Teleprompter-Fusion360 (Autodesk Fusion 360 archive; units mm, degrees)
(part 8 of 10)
sketch "Skizze96" plane through (362.0031, 0, 0) normal (-1, 0, 0) x axis (0, -1, 0)
  line L1 (-176.4327, 90.6042) -> (-137.2147, 129.8223)
  line L2 (-156.4445, 183.2864) -> (-195.6625, 104.4333)
  line L3 (-133.7, 138.3075) -> (-133.7, 177.9426)
  line L4 (-97.7, 235.8456) -> (-97.7, 198.3075)
  line L5 (-45.7711, 251.1832) -> (-86.6874, 247.805)
  line L6 (-77.2147, 189.8223) -> (-36.2984, 230.7386)
  line L7 (-117.4574, 213.455) -> (-113.9426, 213.455)
  line L8 (-121.7, 240.7124) -> (-121.7, 217.6976)
  line L9 (-113.9426, 244.955) -> (-117.4574, 244.955)
  line L10 (-109.7, 217.6976) -> (-109.7, 240.7124)
  line L11 (-121.7, 177.7124) -> (-121.7, 154.6976)
  line L12 (-113.9426, 181.955) -> (-117.4574, 181.955)
  line L13 (-109.7, 154.6976) -> (-109.7, 177.7124)
  line L14 (-117.4574, 150.455) -> (-113.9426, 150.455)
  line L15 (16.2993, 266.6485) -> (-239.478, 10.8712)
  line L16 (0.4576, 267) -> (14.6596, 267)
  line L17 (-121.7, 256.955) -> (-0.5298, 266.9593)
  line L18 (-126.9563, 256.521) -> (-123.6681, 256.7925)
  line L19 (-253.9338, 29.6373) -> (-136.5623, 250.199)
  line L20 (-255.3404, 12) -> (-255.3404, 24)
  line L21 (-244.4304, 12) -> (-255.3404, 12)
  line L22 (3.2487, 270) -> (14.6596, 270)
  line L23 (3.2487, 267) -> (3.2487, 270)
  line L24 (14.6596, 267) -> (10.2487, 267)
  line L25 (18.6596, 263.0692) -> (18.659, 263.0698)
  line L26 (18.659, 263.0686) -> (18.6596, 263.0692)
  line L27 (18.6596, 251.0692) -> (18.6596, 263)
  line L28 (15.1903, 238.3866) -> (13.069, 240.508)
  line L29 (17.2662, 240.4626) -> (15.1903, 238.3866)
  line L30 (21.6596, 263) -> (21.6596, 251.0692)
  line L31 (-169.9972, 18) -> (-214.6835, 18)
  line L32 (-164.3404, 0) -> (-164.3404, 14.2357)
  line L33 (-130.1404, 0) -> (-164.3404, 0)
  line L34 (-130.1404, 7.7574) -> (-130.1404, 0)
  line L35 (-100.183, 12) -> (-125.8977, 12)
  line L36 (-95.9404, 0) -> (-95.9404, 7.7574)
  line L37 (-61.7404, 0) -> (-95.9404, 0)
  line L38 (-61.7404, 7.7574) -> (-61.7404, 0)
  line L39 (-31.783, 12) -> (-57.4977, 12)
  line L40 (-27.5404, 0) -> (-27.5404, 7.7574)
  line L41 (6.6596, 0) -> (-27.5404, 0)
  line L42 (6.6596, 15) -> (6.6596, 0)
  line L43 (-58.0916, 27) -> (-5.3404, 27)
  line L44 (-70.0916, 152.3769) -> (-70.0916, 39)
  line L45 (15.1449, 242.5839) -> (-66.5768, 160.8622)
  line L46 (18.6596, 262.7863) -> (18.6596, 251.0692)
  line L47 (-240.1877, 3.939) -> (18.6596, 262.7863)
  line L48 (-240.1877, 0) -> (-240.1877, 3.939)
  line L49 (-220.3404, 0) -> (-240.1877, 0)
  line L50 (-220.3404, 14.2357) -> (-220.3404, 0)
  line L51 (-159.4684, 39) -> (-106.0916, 39)
  line L52 (-114.5768, 112.8622) -> (-167.9537, 59.4853)
  line L53 (-94.0916, 51) -> (-94.0916, 104.3769)
  line L54 (-240.1877, 3.939) -> (-240.1877, 7.7574)
  line L55 (18.6596, 262.7863) -> (-240.1877, 3.939)
  line L56 (18.6596, 263) -> (18.6596, 262.7863)
  line L57 (-239.478, 10.8712) -> (16.2993, 266.6485)
  circle C1 centre (-115.7, 197.705) radius 1.5
  arc A1 centre (-184.918, 99.0895) radius 12 clockwise from (-176.4327, 90.6042) to (-195.6625, 104.4333)
  arc A2 centre (-145.7, 177.9426) radius 12 clockwise from (-156.4445, 183.2864) to (-133.7, 177.9426)
  arc A3 centre (-145.7, 138.3075) radius 12 clockwise from (-133.7, 138.3075) to (-137.2147, 129.8223)
  arc A4 centre (-85.7, 235.8456) radius 12 clockwise from (-97.7, 235.8456) to (-86.6874, 247.805)
  arc A5 centre (-44.7837, 239.2239) radius 12 clockwise from (-45.7711, 251.1832) to (-36.2984, 230.7386)
  arc A6 centre (-85.7, 198.3075) radius 12 clockwise from (-77.2147, 189.8223) to (-97.7, 198.3075)
  arc A7 centre (-119.5787, 215.5763) radius 3 clockwise from (-117.4574, 213.455) to (-121.7, 217.6976)
  arc A8 centre (-119.5787, 242.8337) radius 3 clockwise from (-121.7, 240.7124) to (-117.4574, 244.955)
  arc A9 centre (-111.8213, 242.8337) radius 3 clockwise from (-113.9426, 244.955) to (-109.7, 240.7124)
  arc A10 centre (-111.8213, 215.5763) radius 3 clockwise from (-109.7, 217.6976) to (-113.9426, 213.455)
  arc A11 centre (-119.5787, 179.8337) radius 3 clockwise from (-121.7, 177.7124) to (-117.4574, 181.955)
  arc A12 centre (-111.8213, 179.8337) radius 3 clockwise from (-113.9426, 181.955) to (-109.7, 177.7124)
  arc A13 centre (-111.8213, 152.5763) radius 3 clockwise from (-109.7, 154.6976) to (-113.9426, 150.455)
  arc A14 centre (-119.5787, 152.5763) radius 3 clockwise from (-117.4574, 150.455) to (-121.7, 154.6976)
  arc A15 centre (-242.3091, 9.8787) radius 3 clockwise from (-244.4304, 12) to (-239.478, 10.8712)
  arc A16 centre (14.6596, 263) radius 4 clockwise from (14.6596, 267) to (16.2993, 266.6485)
  arc A17 centre (0.4576, 255) radius 12 clockwise from (-0.5298, 266.9593) to (0.4576, 267)
  arc A18 centre (-121.7, 244.955) radius 12 clockwise from (-123.6681, 256.7925) to (-121.7, 256.955)
  arc A19 centre (-125.9689, 244.5617) radius 12 clockwise from (-136.5623, 250.199) to (-126.9563, 256.521)
  arc A20 centre (-243.3404, 24) radius 12 clockwise from (-255.3404, 24) to (-253.9338, 29.6373)
  arc A21 centre (14.6596, 263) radius 7 clockwise from (14.6596, 270) to (21.6596, 263)
  arc A22 centre (6.7487, 267) radius 3.5 clockwise from (10.2487, 267) to (3.2487, 267)
  arc A23 centre (14.6596, 263) radius 4 clockwise from (14.6596, 267) to (18.659, 263.0698)
  arc A24 centre (14.6596, 263) radius 4 clockwise from (18.659, 263.0686) to (18.6596, 263)
  arc A25 centre (6.6596, 251.0692) radius 12 clockwise from (18.6596, 251.0692) to (17.4864, 245.8942)
  arc A26 centre (15.5438, 242.9828) radius 3.5 clockwise from (13.069, 240.508) to (17.4864, 245.8942)
  arc A27 centre (6.6596, 251.0692) radius 15 clockwise from (21.6596, 251.0692) to (17.2662, 240.4626)
  arc A28 centre (6.7487, 267) radius 3.75 clockwise from (10.4987, 267) to (2.9987, 267)
  circle C2 centre (15.5438, 242.9828) radius 3.75
  arc A29 centre (-214.6835, 10) radius 8 clockwise from (-218.9345, 16.7771) to (-214.6835, 18)
  arc A30 centre (-169.9972, 10) radius 8 clockwise from (-169.9972, 18) to (-165.7463, 16.7771)
  arc A31 centre (-167.3404, 14.2357) radius 3 clockwise from (-165.7463, 16.7771) to (-164.3404, 14.2357)
  arc A32 centre (-128.0191, 9.8787) radius 3 clockwise from (-130.1404, 7.7574) to (-125.8977, 12)
  arc A33 centre (-98.0617, 9.8787) radius 3 clockwise from (-100.183, 12) to (-95.9404, 7.7574)
  arc A34 centre (-59.6191, 9.8787) radius 3 clockwise from (-61.7404, 7.7574) to (-57.4977, 12)
  arc A35 centre (-29.6617, 9.8787) radius 3 clockwise from (-31.783, 12) to (-27.5404, 7.7574)
  arc A36 centre (-5.3404, 15) radius 12 clockwise from (-5.3404, 27) to (6.6596, 15)
  arc A37 centre (-58.0916, 39) radius 12 clockwise from (-58.0916, 27) to (-70.0916, 39)
  arc A38 centre (-58.0916, 152.3769) radius 12 clockwise from (-70.0916, 152.3769) to (-66.5768, 160.8622)
  arc A39 centre (6.6596, 251.0692) radius 12 clockwise from (18.6596, 251.0692) to (15.1449, 242.5839)
  arc A40 centre (-217.3404, 14.2357) radius 3 clockwise from (-220.3404, 14.2357) to (-218.9345, 16.7771)
  circle C3 centre (-140.2404, 6) radius 1.5
  arc A41 centre (-159.4684, 51) radius 12 clockwise from (-159.4684, 39) to (-167.9537, 59.4853)
  arc A42 centre (-106.0916, 104.3769) radius 12 clockwise from (-114.5768, 112.8622) to (-94.0916, 104.3769)
  arc A43 centre (-106.0916, 51) radius 12 clockwise from (-94.0916, 51) to (-106.0916, 39)
  circle C4 centre (-230.2641, 6) radius 1.5
  circle C5 centre (-10.4404, 6) radius 1.5
  circle C6 centre (-78.8404, 6) radius 1.5
  arc A44 centre (-242.3091, 9.8787) radius 3 clockwise from (-239.478, 10.8712) to (-240.1877, 7.7574)
  arc A45 centre (14.6596, 263) radius 4 clockwise from (16.2993, 266.6485) to (18.6596, 263)
  point P85 (10.4987, 267)
  point P86 (2.9987, 267)
  concentric A22 A28
  coincident L16 P85
  coincident L16 P86
  concentric A26 C2
  dimension "d545" diameter A28 = 7.5
  dimension "d547" diameter C2 = 7.5
extrude "Extrusion97" cut sketch "Skizze96" profile of L16 A22 L24 A25 A26 A28 C2 L45 A39 against normal blind 14
mirror "Spiegeln4" mirrorStitchTolerance 0.1 bodies "3DP-Glas-Abdeckung Left"
sketch "Skizze97" plane through (-2.9969, 0, 0) normal (1, 0, 0) x axis (0, 1, 0)
  line L1 (137.2147, 129.8223) -> (176.4327, 90.6042)
  line L2 (133.7, 177.9426) -> (133.7, 138.3075)
  line L3 (195.6625, 104.4333) -> (156.4445, 183.2864)
  line L4 (97.7, 198.3075) -> (97.7, 235.8456)
  line L5 (36.2984, 230.7386) -> (77.2147, 189.8223)
  line L6 (86.6874, 247.805) -> (45.7711, 251.1832)
  line L7 (113.9426, 213.455) -> (117.4574, 213.455)
  line L8 (109.7, 240.7124) -> (109.7, 217.6976)
  line L9 (117.4574, 244.955) -> (113.9426, 244.955)
  line L10 (121.7, 217.6976) -> (121.7, 240.7124)
  line L11 (121.7, 154.6976) -> (121.7, 177.7124)
  line L12 (113.9426, 150.455) -> (117.4574, 150.455)
  line L13 (109.7, 177.7124) -> (109.7, 154.6976)
  line L14 (117.4574, 181.955) -> (113.9426, 181.955)
  line L15 (255.3404, 12) -> (244.4304, 12)
  line L16 (255.3404, 24) -> (255.3404, 12)
  line L17 (136.5623, 250.199) -> (253.9338, 29.6373)
  line L18 (123.6681, 256.7925) -> (126.9563, 256.521)
  line L19
  line L20 (-14.6596, 267) -> (-0.4576, 267)
  line L21 (239.478, 10.8712) -> (-16.2993, 266.6485)
  line L22 (106.0916, 39) -> (159.4684, 39)
  line L23 (94.0916, 104.3769) -> (94.0916, 51)
  line L24 (167.9537, 59.4853) -> (114.5768, 112.8622)
  line L25 (130.1404, 0) -> (130.1404, 7.7574)
  line L26 (164.3404, 0) -> (130.1404, 0)
  line L27 (164.3404, 11.3932) -> (164.3404, 0)
  line L28 (214.6835, 16) -> (169.9972, 16)
  line L29 (220.3404, 0) -> (220.3404, 11.3932)
  line L30 (240.1877, 0) -> (220.3404, 0)
  line L31 (240.1877, 3.939) -> (240.1877, 0)
  line L32 (-18.6596, 262.7863) -> (240.1877, 3.939)
  line L33 (-18.6596, 251.0692) -> (-18.6596, 262.7863)
  line L34 (66.5768, 160.8622) -> (-15.1449, 242.5839)
  line L35 (70.0916, 39) -> (70.0916, 152.3769)
  line L36 (5.3404, 27) -> (58.0916, 27)
  line L37 (-6.6596, 0) -> (-6.6596, 15)
  line L38 (27.5404, 0) -> (-6.6596, 0)
  line L39 (27.5404, 7.7574) -> (27.5404, 0)
  line L40 (57.4977, 12) -> (31.783, 12)
  line L41 (61.7404, 0) -> (61.7404, 7.7574)
  line L42 (95.9404, 0) -> (61.7404, 0)
  line L43 (95.9404, 7.7574) -> (95.9404, 0)
  line L44 (125.8977, 12) -> (100.183, 12)
  line L45 (-16.2993, 266.6485) -> (239.478, 10.8712)
  line L46 (-18.6596, 262.7863) -> (-18.6596, 263)
  line L47 (240.1877, 3.939) -> (-18.6596, 262.7863)
  line L48 (240.1877, 7.7574) -> (240.1877, 3.939)
  circle C1 centre (115.7, 197.705) radius 1.5
  arc A1 centre (145.7, 138.3075) radius 12 clockwise from (137.2147, 129.8223) to (133.7, 138.3075)
  arc A2 centre (145.7, 177.9426) radius 12 clockwise from (133.7, 177.9426) to (156.4445, 183.2864)
  arc A3 centre (184.918, 99.0895) radius 12 clockwise from (195.6625, 104.4333) to (176.4327, 90.6042)
  arc A4 centre (85.7, 198.3075) radius 12 clockwise from (97.7, 198.3075) to (77.2147, 189.8223)
  arc A5 centre (44.7837, 239.2239) radius 12 clockwise from (36.2984, 230.7386) to (45.7711, 251.1832)
  arc A6 centre (85.7, 235.8456) radius 12 clockwise from (86.6874, 247.805) to (97.7, 235.8456)
  arc A7 centre (111.8213, 215.5763) radius 3 clockwise from (113.9426, 213.455) to (109.7, 217.6976)
  arc A8 centre (111.8213, 242.8337) radius 3 clockwise from (109.7, 240.7124) to (113.9426, 244.955)
  arc A9 centre (119.5787, 242.8337) radius 3 clockwise from (117.4574, 244.955) to (121.7, 240.7124)
  arc A10 centre (119.5787, 215.5763) radius 3 clockwise from (121.7, 217.6976) to (117.4574, 213.455)
  arc A11 centre (119.5787, 152.5763) radius 3 clockwise from (121.7, 154.6976) to (117.4574, 150.455)
  arc A12 centre (111.8213, 152.5763) radius 3 clockwise from (113.9426, 150.455) to (109.7, 154.6976)
  arc A13 centre (111.8213, 179.8337) radius 3 clockwise from (109.7, 177.7124) to (113.9426, 181.955)
  arc A14 centre (119.5787, 179.8337) radius 3 clockwise from (117.4574, 181.955) to (121.7, 177.7124)
  arc A15 centre (242.3091, 9.8787) radius 3 clockwise from (239.478, 10.8712) to (244.4304, 12)
  arc A16 centre (243.3404, 24) radius 12 clockwise from (253.9338, 29.6373) to (255.3404, 24)
  arc A17 centre (125.9689, 244.5617) radius 12 clockwise from (126.9563, 256.521) to (136.5623, 250.199)
  arc A18 centre (121.7, 244.955) radius 12 clockwise from (121.7, 256.955) to (123.6681, 256.7925)
  arc A19 centre (-0.4576, 255) radius 12 clockwise from (-0.4576, 267) to (0.5298, 266.9593)
  arc A20 centre (-14.6596, 263) radius 4 clockwise from (-16.2993, 266.6485) to (-14.6596, 267)
  arc A21 centre (-6.7487, 267) radius 3.75 clockwise from (-2.9987, 267) to (-10.4987, 267)
  arc A22 centre (-15.5438, 242.9828) radius 3.75 clockwise from (-17.593, 246.1234) to (-12.8922, 240.3312)
  circle C2 centre (140.2404, 6) radius 1.5
  arc A23 centre (106.0916, 51) radius 12 clockwise from (106.0916, 39) to (94.0916, 51)
  arc A24 centre (106.0916, 104.3769) radius 12 clockwise from (94.0916, 104.3769) to (114.5768, 112.8622)
  arc A25 centre (159.4684, 51) radius 12 clockwise from (167.9537, 59.4853) to (159.4684, 39)
  circle C3 centre (230.2641, 6) radius 1.5
  circle C4 centre (10.4404, 6) radius 1.5
  circle C5 centre (78.8404, 6) radius 1.5
  arc A26 centre (128.0191, 9.8787) radius 3 clockwise from (125.8977, 12) to (130.1404, 7.7574)
  arc A27 centre (167.3404, 11.3932) radius 3 clockwise from (164.3404, 11.3932) to (164.6835, 12.7865)
  arc A28 centre (169.9972, 10) radius 6 clockwise from (164.6835, 12.7865) to (169.9972, 16)
  arc A29 centre (214.6835, 10) radius 6 clockwise from (214.6835, 16) to (219.9972, 12.7865)
  arc A30 centre (217.3404, 11.3932) radius 3 clockwise from (219.9972, 12.7865) to (220.3404, 11.3932)
  arc A31 centre (-6.6596, 251.0692) radius 12 clockwise from (-15.1449, 242.5839) to (-18.6596, 251.0692)
  arc A32 centre (58.0916, 152.3769) radius 12 clockwise from (66.5768, 160.8622) to (70.0916, 152.3769)
  arc A33 centre (58.0916, 39) radius 12 clockwise from (70.0916, 39) to (58.0916, 27)
  arc A34 centre (5.3404, 15) radius 12 clockwise from (-6.6596, 15) to (5.3404, 27)
  arc A35 centre (29.6617, 9.8787) radius 3 clockwise from (27.5404, 7.7574) to (31.783, 12)
  arc A36 centre (59.6191, 9.8787) radius 3 clockwise from (57.4977, 12) to (61.7404, 7.7574)
  arc A37 centre (98.0617, 9.8787) radius 3 clockwise from (95.9404, 7.7574) to (100.183, 12)
  arc A38 centre (242.3091, 9.8787) radius 3 clockwise from (240.1877, 7.7574) to (239.478, 10.8712)
  arc A39 centre (-14.6596, 263) radius 4 clockwise from (-18.6596, 263) to (-16.2993, 266.6485)
extrude "Extrusion98" cut sketch "Skizze97" profile of L20 A21 A22 A31 L34 against normal blind 16
chamfer "Fase12" distance 2 distance 6
chamfer "Fase13" distance 6 distance 2
sketch "Skizze98" plane through (0, 0, 0) normal (0, 0, -1) x axis (1, 0, 0)
  line L1 (47.0031, -126.3404) -> (155.5031, -126.3404)
  line L2 (35.0031, -31.3404) -> (35.0031, -114.3404)
  line L3 (155.5031, -19.3404) -> (47.0031, -19.3404)
  line L4 (167.5031, -114.3404) -> (167.5031, -31.3404)
  line L5 (71.0031, -202.3404) -> (155.5031, -202.3404)
  line L6 (59.0031, -174.3404) -> (59.0031, -190.3404)
  line L7 (155.5031, -162.3404) -> (71.0031, -162.3404)
  line L8 (167.5031, -190.3404) -> (167.5031, -174.3404)
  line L9 (191.5031, -31.3404) -> (191.5031, -114.3404)
  line L10 (312.0031, -19.3404) -> (203.5031, -19.3404)
  line L11 (324.0031, -114.3404) -> (324.0031, -31.3404)
  line L12 (203.5031, -126.3404) -> (312.0031, -126.3404)
  line L13 (300.0031, -190.3404) -> (300.0031, -174.3404)
  line L14 (203.5031, -202.3404) -> (288.0031, -202.3404)
  line L15 (191.5031, -174.3404) -> (191.5031, -190.3404)
  line L16 (288.0031, -162.3404) -> (203.5031, -162.3404)
  line L17 (137.0031, -323.7) -> (137.0031, -279.3404)
  line L18 (154.0031, -323.7) -> (137.0031, -323.7)
  line L19 (154.0031, -311.7) -> (154.0031, -323.7)
  line L20 (171.0031, -311.7) -> (154.0031, -311.7)
  line L21 (171.0031, -323.7) -> (171.0031, -311.7)
  line L22 (188.0031, -323.7) -> (171.0031, -323.7)
  line L23 (188.0031, -311.7) -> (188.0031, -323.7)
  line L24 (205.0031, -311.7) -> (188.0031, -311.7)
  line L25 (205.0031, -323.7) -> (205.0031, -311.7)
  line L26 (222.0031, -323.7) -> (205.0031, -323.7)
  line L27 (222.0031, -279.3404) -> (222.0031, -323.7)
  line L28 (374.0031, -255.3404) -> (246.0031, -255.3404)
  line L29 (374.0031, -240.1877) -> (374.0031, -255.3404)
  line L30 (366.2457, -240.1877) -> (374.0031, -240.1877)
  line L31 (362.0031, -220.3404) -> (362.0031, -235.9451)
  line L32 (361.0031, -220.3404) -> (362.0031, -220.3404)
  line L33 (358.0031, -167.3404) -> (358.0031, -217.3404)
  line L34 (362.0031, -164.3404) -> (361.0031, -164.3404)
  line L35 (362.0031, -134.383) -> (362.0031, -164.3404)
  line L36 (374.0031, -130.1404) -> (366.2457, -130.1404)
  line L37 (374.0031, -95.9404) -> (374.0031, -130.1404)
  line L38 (366.2457, -95.9404) -> (374.0031, -95.9404)
  line L39 (362.0031, -65.983) -> (362.0031, -91.6977)
  line L40 (374.0031, -61.7404) -> (366.2457, -61.7404)
  line L41 (374.0031, -27.5404) -> (374.0031, -61.7404)
  line L42 (366.2457, -27.5404) -> (374.0031, -27.5404)
  line L43 (362.0031, 2.417) -> (362.0031, -23.2977)
  line L44 (374.0031, 6.6596) -> (366.2457, 6.6596)
  line L45 (-2.9969, 18.6596) -> (362.0031, 18.6596)
  line L46 (-7.2396, 6.6596) -> (-14.9969, 6.6596)
  line L47 (-2.9969, -23.2977) -> (-2.9969, 2.417)
  line L48 (-14.9969, -27.5404) -> (-7.2396, -27.5404)
  line L49 (-14.9969, -61.7404) -> (-14.9969, -27.5404)
  line L50 (-7.2396, -61.7404) -> (-14.9969, -61.7404)
  line L51 (-2.9969, -91.6977) -> (-2.9969, -65.983)
  line L52 (-14.9969, -95.9404) -> (-7.2396, -95.9404)
  line L53 (-14.9969, -130.1404) -> (-14.9969, -95.9404)
  line L54 (-7.2396, -130.1404) -> (-14.9969, -130.1404)
  line L55 (-2.9969, -164.3404) -> (-2.9969, -134.383)
  line L56 (-2.9968, -164.3404) -> (-2.9969, -164.3404)
  line L57 (0.0031, -217.3404) -> (0.0031, -167.3404)
  line L58 (-2.9969, -220.3404) -> (-2.9968, -220.3404)
  line L59 (-2.9969, -235.9451) -> (-2.9969, -220.3404)
  line L60 (-14.9969, -240.1877) -> (-7.2396, -240.1877)
  line L61 (-14.9969, -255.3404) -> (-14.9969, -240.1877)
  line L62 (113.0031, -255.3404) -> (-14.9969, -255.3404)
  circle C1 centre (-8.9969, -113.0404) radius 4.5
  circle C2 centre (368.0031, -246.1877) radius 4.5
  circle C3 centre (368.0031, -44.6404) radius 4.5
  circle C4 centre (179.5031, -317.7) radius 4.5
  arc A1 centre (47.0031, -114.3404) radius 12 clockwise from (47.0031, -126.3404) to (35.0031, -114.3404)
  arc A2 centre (47.0031, -31.3404) radius 12 clockwise from (35.0031, -31.3404) to (47.0031, -19.3404)
  arc A3 centre (155.5031, -31.3404) radius 12 clockwise from (155.5031, -19.3404) to (167.5031, -31.3404)
  arc A4 centre (155.5031, -114.3404) radius 12 clockwise from (167.5031, -114.3404) to (155.5031, -126.3404)
  arc A5 centre (71.0031, -190.3404) radius 12 clockwise from (71.0031, -202.3404) to (59.0031, -190.3404)
  arc A6 centre (71.0031, -174.3404) radius 12 clockwise from (59.0031, -174.3404) to (71.0031, -162.3404)
  arc A7 centre (155.5031, -174.3404) radius 12 clockwise from (155.5031, -162.3404) to (167.5031, -174.3404)
  arc A8 centre (155.5031, -190.3404) radius 12 clockwise from (167.5031, -190.3404) to (155.5031, -202.3404)
  arc A9 centre (203.5031, -31.3404) radius 12 clockwise from (191.5031, -31.3404) to (203.5031, -19.3404)
  arc A10 centre (312.0031, -31.3404) radius 12 clockwise from (312.0031, -19.3404) to (324.0031, -31.3404)
  arc A11 centre (312.0031, -114.3404) radius 12 clockwise from (324.0031, -114.3404) to (312.0031, -126.3404)
  arc A12 centre (203.5031, -114.3404) radius 12 clockwise from (203.5031, -126.3404) to (191.5031, -114.3404)
  arc A13 centre (288.0031, -190.3404) radius 12 clockwise from (300.0031, -190.3404) to (288.0031, -202.3404)
  arc A14 centre (203.5031, -190.3404) radius 12 clockwise from (203.5031, -202.3404) to (191.5031, -190.3404)
  arc A15 centre (203.5031, -174.3404) radius 12 clockwise from (191.5031, -174.3404) to (203.5031, -162.3404)
  arc A16 centre (288.0031, -174.3404) radius 12 clockwise from (288.0031, -162.3404) to (300.0031, -174.3404)
  arc A17 centre (246.0031, -279.3404) radius 24 clockwise from (222.0031, -279.3404) to (246.0031, -255.3404)
  arc A18 centre (364.1244, -238.0664) radius 3 clockwise from (366.2457, -240.1877) to (362.0031, -235.9451)
  arc A19 centre (361.0031, -217.3404) radius 3 clockwise from (361.0031, -220.3404) to (358.0031, -217.3404)
  arc A20 centre (361.0031, -167.3404) radius 3 clockwise from (358.0031, -167.3404) to (361.0031, -164.3404)
  arc A21 centre (364.1244, -132.2617) radius 3 clockwise from (362.0031, -134.383) to (366.2457, -130.1404)
  arc A22 centre (364.1244, -93.8191) radius 3 clockwise from (366.2457, -95.9404) to (362.0031, -91.6977)
  arc A23 centre (364.1244, -63.8617) radius 3 clockwise from (362.0031, -65.983) to (366.2457, -61.7404)
  arc A24 centre (364.1244, -25.4191) radius 3 clockwise from (366.2457, -27.5404) to (362.0031, -23.2977)
  arc A25 centre (364.1244, 4.5383) radius 3 clockwise from (362.0031, 2.417) to (366.2457, 6.6596)
  arc A26 centre (362.0031, 6.6596) radius 12 clockwise from (362.0031, 18.6596) to (374.0031, 6.6596)
  arc A27 centre (-2.9969, 6.6596) radius 12 clockwise from (-14.9969, 6.6596) to (-2.9969, 18.6596)
  arc A28 centre (-5.1183, 4.5383) radius 3 clockwise from (-7.2396, 6.6596) to (-2.9969, 2.417)
  arc A29 centre (-5.1183, -25.4191) radius 3 clockwise from (-2.9969, -23.2977) to (-7.2396, -27.5404)
  arc A30 centre (-5.1183, -63.8617) radius 3 clockwise from (-7.2396, -61.7404) to (-2.9969, -65.983)
  arc A31 centre (-5.1183, -93.8191) radius 3 clockwise from (-2.9969, -91.6977) to (-7.2396, -95.9404)
  arc A32 centre (-5.1183, -132.2617) radius 3 clockwise from (-7.2396, -130.1404) to (-2.9969, -134.383)
  arc A33 centre (-2.9969, -167.3404) radius 3 clockwise from (-2.9968, -164.3404) to (0.0031, -167.3404)
  arc A34 centre (-2.9969, -217.3404) radius 3 clockwise from (0.0031, -217.3404) to (-2.9968, -220.3404)
  arc A35 centre (-5.1183, -238.0664) radius 3 clockwise from (-2.9969, -235.9451) to (-7.2396, -240.1877)
  arc A36 centre (113.0031, -279.3404) radius 24 clockwise from (113.0031, -255.3404) to (137.0031, -279.3404)
  circle C5 centre (213.5031, -317.7) radius 4.5
  circle C6 centre (145.5031, -317.7) radius 4.5
  circle C7 centre (368.0031, -113.0404) radius 4.5
  circle C8 centre (-8.9969, -44.6404) radius 4.5
  circle C9 centre (-8.9969, -246.1877) radius 4.5
extrude "Extrusion99" add sketch "Skizze98" profile of L5 A5 L6 A6 L7 A7 L8 A8 L13 A13 L14 A14 L15 A15 L16 A16 to an object
sketch "Skizze99" plane through (0, 0, 0) normal (0, 0, -1) x axis (1, 0, 0)
  line L1 (47.0031, -126.3404) -> (155.5031, -126.3404)
  line L2 (35.0031, -31.3404) -> (35.0031, -114.3404)
  line L3 (155.5031, -19.3404) -> (47.0031, -19.3404)
  line L4 (167.5031, -114.3404) -> (167.5031, -31.3404)
  line L5 (191.5031, -31.3404) -> (191.5031, -114.3404)
  line L6 (312.0031, -19.3404) -> (203.5031, -19.3404)
  line L7 (324.0031, -114.3404) -> (324.0031, -31.3404)
  line L8 (203.5031, -126.3404) -> (312.0031, -126.3404)
  line L9 (137.0031, -323.7) -> (137.0031, -279.3404)
  line L10 (154.0031, -323.7) -> (137.0031, -323.7)
  line L11 (154.0031, -311.7) -> (154.0031, -323.7)
  line L12 (171.0031, -311.7) -> (154.0031, -311.7)
  line L13 (171.0031, -323.7) -> (171.0031, -311.7)
  line L14 (188.0031, -323.7) -> (171.0031, -323.7)
  line L15 (188.0031, -311.7) -> (188.0031, -323.7)
  line L16 (205.0031, -311.7) -> (188.0031, -311.7)
  line L17 (205.0031, -323.7) -> (205.0031, -311.7)
  line L18 (222.0031, -323.7) -> (205.0031, -323.7)
  line L19 (222.0031, -279.3404) -> (222.0031, -323.7)
  line L20 (374.0031, -255.3404) -> (246.0031, -255.3404)
  line L21 (374.0031, -240.1877) -> (374.0031, -255.3404)
  line L22 (366.2457, -240.1877) -> (374.0031, -240.1877)
  line L23 (362.0031, -220.3404) -> (362.0031, -235.9451)
  line L24 (361.0031, -220.3404) -> (362.0031, -220.3404)
  line L25 (358.0031, -167.3404) -> (358.0031, -217.3404)
  line L26 (362.0031, -164.3404) -> (361.0031, -164.3404)
  line L27 (362.0031, -134.383) -> (362.0031, -164.3404)
  line L28 (374.0031, -130.1404) -> (366.2457, -130.1404)
  line L29 (374.0031, -95.9404) -> (374.0031, -130.1404)
  line L30 (366.2457, -95.9404) -> (374.0031, -95.9404)
  line L31 (362.0031, -65.983) -> (362.0031, -91.6977)
  line L32 (374.0031, -61.7404) -> (366.2457, -61.7404)
  line L33 (374.0031, -27.5404) -> (374.0031, -61.7404)
  line L34 (366.2457, -27.5404) -> (374.0031, -27.5404)
  line L35 (362.0031, 2.417) -> (362.0031, -23.2977)
  line L36 (374.0031, 6.6596) -> (366.2457, 6.6596)
  line L37 (-2.9969, 18.6596) -> (362.0031, 18.6596)
  line L38 (-7.2396, 6.6596) -> (-14.9969, 6.6596)
  line L39 (-2.9969, -23.2977) -> (-2.9969, 2.417)
  line L40 (-14.9969, -27.5404) -> (-7.2396, -27.5404)
  line L41 (-14.9969, -61.7404) -> (-14.9969, -27.5404)
  line L42 (-7.2396, -61.7404) -> (-14.9969, -61.7404)
  line L43 (-2.9969, -91.6977) -> (-2.9969, -65.983)
  line L44 (-14.9969, -95.9404) -> (-7.2396, -95.9404)
  line L45 (-14.9969, -130.1404) -> (-14.9969, -95.9404)
  line L46 (-7.2396, -130.1404) -> (-14.9969, -130.1404)
  line L47 (-2.9969, -164.3404) -> (-2.9969, -134.383)
  line L48 (-2.9968, -164.3404) -> (-2.9969, -164.3404)
  line L49 (0.0031, -217.3404) -> (0.0031, -167.3404)
  line L50 (-2.9969, -220.3404) -> (-2.9968, -220.3404)
  line L51 (-2.9969, -235.9451) -> (-2.9969, -220.3404)
  line L52 (-14.9969, -240.1877) -> (-7.2396, -240.1877)
  line L53 (-14.9969, -255.3404) -> (-14.9969, -240.1877)
  line L54 (113.0031, -255.3404) -> (-14.9969, -255.3404)
  line L55 (282.0031, -255.3404) -> (77.0031, -255.3404)
  line L56 (282.0031, -126.3404) -> (282.0031, -255.3404)
  line L57 (77.0031, -126.3404) -> (282.0031, -126.3404)
  line L58 (77.0031, -255.3404) -> (77.0031, -126.3404)
  line L59 (222.0031, -290.3404) -> (137.0031, -290.3404)
  line L60 (191.5031, -91.3404) -> (167.5031, -91.3404)
  circle C1 centre (-8.9969, -113.0404) radius 4.5
  circle C2 centre (368.0031, -246.1877) radius 4.5
  circle C3 centre (368.0031, -44.6404) radius 4.5
  circle C4 centre (179.5031, -317.7) radius 4.5
  arc A1 centre (47.0031, -114.3404) radius 12 clockwise from (47.0031, -126.3404) to (35.0031, -114.3404)
  arc A2 centre (47.0031, -31.3404) radius 12 clockwise from (35.0031, -31.3404) to (47.0031, -19.3404)
  arc A3 centre (155.5031, -31.3404) radius 12 clockwise from (155.5031, -19.3404) to (167.5031, -31.3404)
  arc A4 centre (155.5031, -114.3404) radius 12 clockwise from (167.5031, -114.3404) to (155.5031, -126.3404)
  arc A5 centre (203.5031, -31.3404) radius 12 clockwise from (191.5031, -31.3404) to (203.5031, -19.3404)
  arc A6 centre (312.0031, -31.3404) radius 12 clockwise from (312.0031, -19.3404) to (324.0031, -31.3404)
  arc A7 centre (312.0031, -114.3404) radius 12 clockwise from (324.0031, -114.3404) to (312.0031, -126.3404)
  arc A8 centre (203.5031, -114.3404) radius 12 clockwise from (203.5031, -126.3404) to (191.5031, -114.3404)
  arc A9 centre (246.0031, -279.3404) radius 24 clockwise from (222.0031, -279.3404) to (246.0031, -255.3404)
  arc A10 centre (364.1244, -238.0664) radius 3 clockwise from (366.2457, -240.1877) to (362.0031, -235.9451)
  arc A11 centre (361.0031, -217.3404) radius 3 clockwise from (361.0031, -220.3404) to (358.0031, -217.3404)
  arc A12 centre (361.0031, -167.3404) radius 3 clockwise from (358.0031, -167.3404) to (361.0031, -164.3404)
  arc A13 centre (364.1244, -132.2617) radius 3 clockwise from (362.0031, -134.383) to (366.2457, -130.1404)
  arc A14 centre (364.1244, -93.8191) radius 3 clockwise from (366.2457, -95.9404) to (362.0031, -91.6977)
  arc A15 centre (364.1244, -63.8617) radius 3 clockwise from (362.0031, -65.983) to (366.2457, -61.7404)
  arc A16 centre (364.1244, -25.4191) radius 3 clockwise from (366.2457, -27.5404) to (362.0031, -23.2977)
  arc A17 centre (364.1244, 4.5383) radius 3 clockwise from (362.0031, 2.417) to (366.2457, 6.6596)
  arc A18 centre (362.0031, 6.6596) radius 12 clockwise from (362.0031, 18.6596) to (374.0031, 6.6596)
  arc A19 centre (-2.9969, 6.6596) radius 12 clockwise from (-14.9969, 6.6596) to (-2.9969, 18.6596)
  arc A20 centre (-5.1183, 4.5383) radius 3 clockwise from (-7.2396, 6.6596) to (-2.9969, 2.417)
  arc A21 centre (-5.1183, -25.4191) radius 3 clockwise from (-2.9969, -23.2977) to (-7.2396, -27.5404)
  arc A22 centre (-5.1183, -63.8617) radius 3 clockwise from (-7.2396, -61.7404) to (-2.9969, -65.983)
  arc A23 centre (-5.1183, -93.8191) radius 3 clockwise from (-2.9969, -91.6977) to (-7.2396, -95.9404)
  arc A24 centre (-5.1183, -132.2617) radius 3 clockwise from (-7.2396, -130.1404) to (-2.9969, -134.383)
  arc A25 centre (-2.9969, -167.3404) radius 3 clockwise from (-2.9968, -164.3404) to (0.0031, -167.3404)
  arc A26 centre (-2.9969, -217.3404) radius 3 clockwise from (0.0031, -217.3404) to (-2.9968, -220.3404)
  arc A27 centre (-5.1183, -238.0664) radius 3 clockwise from (-2.9969, -235.9451) to (-7.2396, -240.1877)
  arc A28 centre (113.0031, -279.3404) radius 24 clockwise from (113.0031, -255.3404) to (137.0031, -279.3404)
  circle C5 centre (213.5031, -317.7) radius 4.5
  circle C6 centre (145.5031, -317.7) radius 4.5
  circle C7 centre (368.0031, -113.0404) radius 4.5
  circle C8 centre (-8.9969, -44.6404) radius 4.5
  circle C9 centre (-8.9969, -246.1877) radius 4.5
  point P123 (282.0031, -126.3404)
  point P121 (77.0031, -255.3404)
  point P125 (137.0031, -290.3404)
  point P126 (222.0031, -290.3404)
  point P127 (167.5031, -91.3404)
  point P128 (191.5031, -91.3404)
  horizontal L55
  vertical L56
  horizontal L57
  vertical L58
  coincident L8 P123
  coincident L54 P121
  coincident L9 P125
  coincident L19 P126
  perpendicular L19 L59
  coincident L4 P127
  coincident L5 P128
  perpendicular L5 L60
  dimension "d560" distance L27 L56 = 80
  dimension "d561" distance L47 L58 = 80
  dimension "d562" distance L55 L59 = 35
  dimension "d563" distance L57 L60 = 35
extrude "Extrusion100" new body sketch "Skizze99" profile of L1 L4 A4 L5 L8 A8 L9 L19 A9 L20 L54 A28 L56 L57 L58 L59 L60 along normal blind 12 bodies "Stiffening Base Adapter"
component_insert "Komponente einfügen3"
sketch "Skizze100" plane through (0, 0, 4) normal (0, 0, 1) x axis (-1, 0, 0)
  line L1 (2.9968, -220.3404) -> (2.9969, -220.3404)
  line L2 (-0.0031, -167.3404) -> (-0.0031, -217.3404)
  line L3 (2.9969, -164.3404) -> (2.9968, -164.3404)
  line L4 (2.9969, -150.3404) -> (2.9969, -164.3404)
  line L5 (-362.0031, -150.3404) -> (2.9969, -150.3404)
  line L6 (-362.0031, -164.3404) -> (-362.0031, -150.3404)
  line L7 (-361.0031, -164.3404) -> (-362.0031, -164.3404)
  line L8 (-358.0031, -217.3404) -> (-358.0031, -167.3404)
  line L9 (-362.0031, -220.3404) -> (-361.0031, -220.3404)
  line L10 (-362.0031, -226.3404) -> (-362.0031, -220.3404)
  line L11 (2.9969, -226.3404) -> (-362.0031, -226.3404)
  line L12 (2.9969, -220.3404) -> (2.9969, -226.3404)
  arc A1 centre (2.9969, -217.3404) radius 3 clockwise from (2.9968, -220.3404) to (-0.0031, -217.3404)
  arc A2 centre (2.9969, -167.3404) radius 3 clockwise from (-0.0031, -167.3404) to (2.9968, -164.3404)
  arc A3 centre (-361.0031, -167.3404) radius 3 clockwise from (-361.0031, -164.3404) to (-358.0031, -167.3404)
  arc A4 centre (-361.0031, -217.3404) radius 3 clockwise from (-358.0031, -217.3404) to (-361.0031, -220.3404)
  circle C1 centre (-179.3775, -190) radius 12.5
  circle C2 centre (-179.3775, -190) radius 20
  concentric C1 C2
  dimension "d568" diameter C2 = 40
extrude "Extrusion101" cut sketch "Skizze100" profile of C1 C2 against normal blind 11
sketch "Skizze101" plane through (0, 0, -7) normal (0, 0, 1) x axis (-1, 0, 0)
  circle C1 centre (-179.3775, -190) radius 20
  circle C2 centre (-179.3775, -190) radius 5.05
  concentric C1 C2
  dimension "d569" diameter C2 = 10.1
extrude "Extrusion102" cut sketch "Skizze101" profile of C2 against normal blind 20
sketch "Skizze102" plane through (0, 0, -12) normal (0, 0, -1) x axis (1, 0, 0)
  line L1 (77.0031, -126.3404) -> (155.5031, -126.3404)
  line L2 (77.0031, -255.3404) -> (77.0031, -126.3404)
  line L3 (113.0031, -255.3404) -> (77.0031, -255.3404)
  line L4 (137.0031, -290.3404) -> (137.0031, -279.3404)
  line L5 (222.0031, -290.3404) -> (137.0031, -290.3404)
  line L6 (222.0031, -279.3404) -> (222.0031, -290.3404)
  line L7 (282.0031, -255.3404) -> (246.0031, -255.3404)
  line L8 (282.0031, -126.3404) -> (282.0031, -255.3404)
  line L9 (203.5031, -126.3404) -> (282.0031, -126.3404)
  line L10 (191.5031, -91.3404) -> (191.5031, -114.3404)
  line L11 (167.5031, -91.3404) -> (191.5031, -91.3404)
  line L12 (167.5031, -114.3404) -> (167.5031, -91.3404)
  line L13 (167.5031, -137.4619) -> (167.5031, -91.3404)
  line L14 (191.5031, -137.4619) -> (191.5031, -91.3404)
  line L15 (137.0031, -190) -> (137.0031, -290.3404)
  line L16 (222.0031, -190) -> (222.0031, -290.3404)
  line L17 (137.0031, -190) -> (179.3775, -190)
  circle C1 centre (179.3775, -190) radius 5.05
  arc A1 centre (113.0031, -279.3404) radius 24 clockwise from (113.0031, -255.3404) to (137.0031, -279.3404)
  arc A2 centre (246.0031, -279.3404) radius 24 clockwise from (222.0031, -279.3404) to (246.0031, -255.3404)
  arc A3 centre (203.5031, -114.3404) radius 12 clockwise from (203.5031, -126.3404) to (191.5031, -114.3404)
  arc A4 centre (155.5031, -114.3404) radius 12 clockwise from (167.5031, -114.3404) to (155.5031, -126.3404)
  arc A5 centre (179.5031, -190) radius 42.5 clockwise from (137.0031, -190) to (158.4287, -153.0931)
  arc A6 centre (179.5031, -190) radius 42.5 clockwise from (200.5774, -153.0931) to (222.0031, -190)
  arc A7 centre (149.5031, -137.4619) radius 18 clockwise from (167.5031, -137.4619) to (158.4287, -153.0931)
  arc A8 centre (209.5031, -137.4619) radius 18 clockwise from (200.5774, -153.0931) to (191.5031, -137.4619)
  point P20 (167.5031, -91.3404)
  point P23 (167.5031, -91.3404)
  point P19 (191.5031, -91.3404)
  point P24 (191.5031, -91.3404)
  point P9 (137.0031, -290.3404)
  point P25 (137.0031, -290.3404)
  point P10 (222.0031, -290.3404)
  point P26 (222.0031, -290.3404)
  point P2 (179.3775, -190)
  point P28 (179.3775, -190)
  point P27 (179.5031, -190)
  point P30 (222.0031, -190)
  coincident P20 P23
  perpendicular L11 L13
  coincident P19 P24
  perpendicular L11 L14
  coincident P9 P25
  perpendicular L5 L15
  coincident P10 P26
  perpendicular L5 L16
  tangent L15 A5
  tangent L16 A5
  coincident P2 P28
  perpendicular L15 L17
  coincident P27 L17
  coincident P30 A5
  concentric A5 A6
  tangent L13 A7
  tangent A5 A7
  tangent L14 A8
  tangent A6 A8
  dimension "d573" radius A7 = 18
  dimension "d574" radius A8 = 18
offset_faces "Flächen versetzen4" distance 55
extrude "Extrusion104" add of existing geometry blind 3
sketch "Skizze103" plane through (0, 0, 12) normal (0, 0, 1) x axis (-1, 0, 0)
  line L1 (14.9969, -255.3404) -> (-113.0031, -255.3404)
  line L2 (14.9969, -240.1877) -> (14.9969, -255.3404)
  line L3 (7.2396, -240.1877) -> (14.9969, -240.1877)
  line L4 (-362.0031, -240.1877) -> (2.9969, -240.1877)
  line L5 (-374.0031, -240.1877) -> (-366.2457, -240.1877)
  line L6 (-374.0031, -255.3404) -> (-374.0031, -240.1877)
  line L7 (-246.0031, -255.3404) -> (-374.0031, -255.3404)
  line L8 (-222.0031, -323.7) -> (-222.0031, -279.3404)
  line L9 (-205.0031, -323.7) -> (-222.0031, -323.7)
  line L10 (-205.0031, -311.7) -> (-205.0031, -323.7)
  line L11 (-188.0031, -311.7) -> (-205.0031, -311.7)
  line L12 (-188.0031, -323.7) -> (-188.0031, -311.7)
  line L13 (-171.0031, -323.7) -> (-188.0031, -323.7)
  line L14 (-171.0031, -311.7) -> (-171.0031, -323.7)
  line L15 (-154.0031, -311.7) -> (-171.0031, -311.7)
  line L16 (-154.0031, -323.7) -> (-154.0031, -311.7)
  line L17 (-137.0031, -323.7) -> (-154.0031, -323.7)
  line L18 (-137.0031, -279.3404) -> (-137.0031, -323.7)
  line L19 (-167.5031, -31.3404) -> (-167.5031, -114.3404)
  line L20 (-47.0031, -19.3404) -> (-155.5031, -19.3404)
  line L21 (-35.0031, -114.3404) -> (-35.0031, -31.3404)
  line L22 (-155.5031, -126.3404) -> (-47.0031, -126.3404)
  line L23 (-360.0031, -130.1404) -> (-360.0031, -95.9404)
  line L24 (-362.0031, -130.1404) -> (-360.0031, -130.1404)
  line L25 (-362.0031, -150.3404) -> (-362.0031, -134.383)
  line L26 (2.9969, -150.3404) -> (-362.0031, -150.3404)
  line L27 (2.9969, -134.383) -> (2.9969, -150.3404)
  line L28 (0.9969, -130.1404) -> (2.9969, -130.1404)
  line L29 (0.9969, -95.9404) -> (0.9969, -130.1404)
  line L30 (2.9969, -95.9404) -> (0.9969, -95.9404)
  line L31 (2.9969, -65.983) -> (2.9969, -91.6977)
  line L32 (0.9969, -61.7404) -> (2.9969, -61.7404)
  line L33 (0.9969, -27.5404) -> (0.9969, -61.7404)
  line L34 (2.9969, -27.5404) -> (0.9969, -27.5404)
  line L35 (2.9969, 2.417) -> (2.9969, -23.2977)
  line L36 (-361.1268, 4.6596) -> (2.1207, 4.6596)
  line L37 (-362.0031, -23.2977) -> (-362.0031, 2.417)
  line L38 (-360.0031, -27.5404) -> (-362.0031, -27.5404)
  line L39 (-360.0031, -61.7404) -> (-360.0031, -27.5404)
  line L40 (-362.0031, -61.7404) -> (-360.0031, -61.7404)
  line L41 (-362.0031, -91.6977) -> (-362.0031, -65.983)
  line L42 (-360.0031, -95.9404) -> (-362.0031, -95.9404)
  line L43 (-191.5031, -114.3404) -> (-191.5031, -31.3404)
  line L44 (-312.0031, -126.3404) -> (-203.5031, -126.3404)
  line L45 (-324.0031, -31.3404) -> (-324.0031, -114.3404)
  line L46 (-203.5031, -19.3404) -> (-312.0031, -19.3404)
  line L47 (-77.0031, -126.3404) -> (-155.5031, -126.3404)
  line L48 (-77.0031, -255.3404) -> (-77.0031, -126.3404)
  line L49 (-113.0031, -255.3404) -> (-77.0031, -255.3404)
  line L50 (-137.0031, -290.3404) -> (-137.0031, -279.3404)
  line L51 (-222.0031, -290.3404) -> (-137.0031, -290.3404)
  line L52 (-222.0031, -279.3404) -> (-222.0031, -290.3404)
  line L53 (-282.0031, -255.3404) -> (-246.0031, -255.3404)
  line L54 (-282.0031, -126.3404) -> (-282.0031, -255.3404)
  line L55 (-203.5031, -126.3404) -> (-282.0031, -126.3404)
  line L56 (-191.5031, -36.3404) -> (-191.5031, -114.3404)
  line L57 (-167.5031, -36.3404) -> (-191.5031, -36.3404)
  line L58 (-167.5031, -114.3404) -> (-167.5031, -36.3404)
  line L59 (-246.0031, -255.3404) -> (-113.0031, -255.3404)
  line L60 (-282.0031, -138.3404) -> (-77.0031, -138.3404)
  line L61 (-179.3775, -166.5244) -> (-179.5031, -36.3404)
  line L62 (-203.5031, -19.3404) -> (-155.5031, -19.3404)
  line L63 (-282.0031, -247.7641) -> (-77.0031, -247.7641)
  circle C1 centre (-145.5031, -317.7) radius 1.5
  circle C2 centre (-179.5031, -317.7) radius 1.5
  circle C3 centre (-213.5031, -317.7) radius 1.5
  circle C4 centre (8.9969, -246.1877) radius 1.5
  arc A1 centre (-113.0031, -279.3404) radius 24 clockwise from (-137.0031, -279.3404) to (-113.0031, -255.3404)
  arc A2 centre (5.1183, -238.0664) radius 3 clockwise from (7.2396, -240.1877) to (2.9969, -240.1877)
  arc A3 centre (-364.1244, -238.0664) radius 3 clockwise from (-362.0031, -240.1877) to (-366.2457, -240.1877)
  arc A4 centre (-246.0031, -279.3404) radius 24 clockwise from (-246.0031, -255.3404) to (-222.0031, -279.3404)
  circle C5 centre (-368.0031, -246.1877) radius 1.5
  arc A5 centre (-155.5031, -31.3404) radius 12 clockwise from (-167.5031, -31.3404) to (-155.5031, -19.3404)
  arc A6 centre (-47.0031, -31.3404) radius 12 clockwise from (-47.0031, -19.3404) to (-35.0031, -31.3404)
  arc A7 centre (-47.0031, -114.3404) radius 12 clockwise from (-35.0031, -114.3404) to (-47.0031, -126.3404)
  arc A8 centre (-155.5031, -114.3404) radius 12 clockwise from (-155.5031, -126.3404) to (-167.5031, -114.3404)
  arc A9 centre (-364.1244, -132.2617) radius 3 clockwise from (-362.0031, -130.1404) to (-362.0031, -134.383)
  arc A10 centre (5.1183, -132.2617) radius 3 clockwise from (2.9969, -134.383) to (2.9969, -130.1404)
  arc A11 centre (5.1183, -93.8191) radius 3 clockwise from (2.9969, -95.9404) to (2.9969, -91.6977)
  arc A12 centre (5.1183, -63.8617) radius 3 clockwise from (2.9969, -65.983) to (2.9969, -61.7404)
  arc A13 centre (5.1183, -25.4191) radius 3 clockwise from (2.9969, -27.5404) to (2.9969, -23.2977)
  arc A14 centre (5.1183, 4.5383) radius 3 clockwise from (2.9969, 2.417) to (2.1207, 4.6596)
  arc A15 centre (-364.1244, 4.5383) radius 3 clockwise from (-361.1268, 4.6596) to (-362.0031, 2.417)
  arc A16 centre (-364.1244, -25.4191) radius 3 clockwise from (-362.0031, -23.2977) to (-362.0031, -27.5404)
  arc A17 centre (-364.1244, -63.8617) radius 3 clockwise from (-362.0031, -61.7404) to (-362.0031, -65.983)
  arc A18 centre (-364.1244, -93.8191) radius 3 clockwise from (-362.0031, -91.6977) to (-362.0031, -95.9404)
  arc A19 centre (-203.5031, -114.3404) radius 12 clockwise from (-191.5031, -114.3404) to (-203.5031, -126.3404)
  arc A20 centre (-312.0031, -114.3404) radius 12 clockwise from (-312.0031, -126.3404) to (-324.0031, -114.3404)
  arc A21 centre (-312.0031, -31.3404) radius 12 clockwise from (-324.0031, -31.3404) to (-312.0031, -19.3404)
  arc A22 centre (-203.5031, -31.3404) radius 12 clockwise from (-203.5031, -19.3404) to (-191.5031, -31.3404)
  circle C6 centre (-179.3775, -190) radius 5.05
  arc A23 centre (-113.0031, -279.3404) radius 24 clockwise from (-137.0031, -279.3404) to (-113.0031, -255.3404)
  arc A24 centre (-246.0031, -279.3404) radius 24 clockwise from (-246.0031, -255.3404) to (-222.0031, -279.3404)
  arc A25 centre (-203.5031, -114.3404) radius 12 clockwise from (-191.5031, -114.3404) to (-203.5031, -126.3404)
  arc A26 centre (-155.5031, -114.3404) radius 12 clockwise from (-155.5031, -126.3404) to (-167.5031, -114.3404)
  circle C7 centre (-143.0031, -255.3404) radius 1.5
  circle C8 centre (-216.0031, -255.3404) radius 1.5
  circle C9 centre (-102.0031, -138.3404) radius 1.5
  circle C10 centre (-257.0031, -138.3404) radius 1.5
  circle C11 centre (-179.5031, -138.3404) radius 1.5
  circle C12 centre (-179.4838, -56.3404) radius 1.5
  circle C13 centre (-97.0031, -247.7641) radius 1.5
  circle C14 centre (-262.0031, -247.7641) radius 1.5
  point P101 (-113.0031, -255.3404)
  point P120 (-113.0031, -255.3404)
  point P107 (-246.0031, -255.3404)
  point P121 (-246.0031, -255.3404)
  point P118 (-143.0031, -255.3404)
  point P119 (-216.0031, -255.3404)
  point P124 (-77.0031, -138.3404)
  point P125 (-282.0031, -138.3404)
  point P122 (-102.0031, -138.3404)
  point P123 (-257.0031, -138.3404)
  point P126 (-179.5031, -36.3404)
  point P128 (-179.5031, -138.3404)
  point P129 (-179.4838, -56.3404)
  point P35 (-155.5031, -19.3404)
  point P130 (-155.5031, -19.3404)
  point P95 (-203.5031, -19.3404)
  point P131 (-203.5031, -19.3404)
  point P132 (-77.0031, -247.7641)
  point P133 (-282.0031, -247.7641)
  point P134 (-97.0031, -247.7641)
  point P135 (-262.0031, -247.7641)
  coincident P101 P120
  coincident P107 P121
  coincident P118 L59
  coincident P119 L59
  coincident L48 P124
  coincident L54 P125
  perpendicular L54 L60
  coincident P122 L60
  coincident P123 L60
  midpoint L57 P126
  midpoint L60 P128
  coincident L61 P129
  coincident P35 P130
  coincident P95 P131
  coincident L48 P132
  coincident L54 P133
  perpendicular L54 L63
  coincident L63 P134
  coincident L63 P135
  dimension "d580" diameter C7 = 3
  dimension "d581" diameter C8 = 3
  dimension "d582" distance P118 P120 = 30
  dimension "d583" distance P119 P121 = 30
  dimension "d584" distance L26 L47 = 24
  dimension "d585" diameter C9 = 3
  dimension "d586" diameter C10 = 3
  dimension "d587" distance L55 L60 = 12 (= "24.00 mm / 2")
  dimension "d588" distance P123 P125 = 25
  dimension "d589" distance L48 P122 = 25
  dimension "d590" diameter C11 = 3
  dimension "d595" diameter C12 = 3
  dimension "d597" distance L4 L7 = 15.1527
  dimension "d598" distance L1 L63 = 7.5763 (= "15.1526574565 mm / 2")
  dimension "d599" diameter C13 = 3
  dimension "d600" diameter C14 = 3
  dimension "d601" distance P132 P134 = 20
  dimension "d602" distance L54 P135 = 20 (= "d601")
  dimension "d603" distance L57 P129 = 20
extrude "Extrusion105" cut sketch "Skizze103" profile of C7 C8 C9 C10 C11 C12 C13 C14 against normal blind 80
chamfer "Fase14" distance 3 distance 3
chamfer "Fase15" distance 12 distance 12
sketch "Skizze104" plane through (0, 323.7, 0) normal (0, 1, 0) x axis (-1, 0, 0)
  line L1 (-205.0031, 0) -> (-205.0031, 12)
  line L2 (-188.0031, 0) -> (-205.0031, 0)
  line L3 (-188.0031, 12) -> (-188.0031, 0)
  line L4 (-171.0031, 12) -> (-188.0031, 12)
  line L5 (-171.0031, 0) -> (-171.0031, 12)
  line L6 (-154.0031, 0) -> (-171.0031, 0)
  line L7 (-154.0031, 12) -> (-154.0031, 0)
  line L8 (-137.0031, 12) -> (-154.0031, 12)
  line L9 (-137.0031, 138.455) -> (-137.0031, 12)
  line L10 (-149.6897, 138.455) -> (-137.0031, 138.455)
  line L11 (-154.0031, 150.455) -> (-154.0031, 142.7684)
  line L12 (-171.0031, 150.455) -> (-154.0031, 150.455)
  line L13 (-171.0031, 142.7684) -> (-171.0031, 150.455)
  line L14 (-183.6897, 138.455) -> (-175.3164, 138.455)
  line L15 (-188.0031, 150.455) -> (-188.0031, 142.7684)
  line L16 (-205.0031, 150.455) -> (-188.0031, 150.455)
  line L17 (-205.0031, 142.7684) -> (-205.0031, 150.455)
  line L18 (-222.0031, 138.455) -> (-209.3164, 138.455)
  line L19 (-222.0031, 12) -> (-222.0031, 138.455)
  line L20 (-205.0031, 12) -> (-222.0031, 12)
  line L21 (-210.3367, 6.6663) -> (-205.0031, 12)
  line L22 (-197.4601, 12) -> (-205.0031, 12)
  line L23 (-181.5592, 5.5562) -> (-188.0031, 12)
  line L24 (-178.8901, 12) -> (-188.0031, 12)
  line L25 (-179.5053, 3.4977) -> (-171.0031, 12)
  line L26 (-158.979, 12) -> (-171.0031, 12)
  line L27 (-146.6461, 4.643) -> (-154.0031, 12)
  line L28 (-143.5987, 12) -> (-154.0031, 12)
  circle C1 centre (-162.5031, 6) radius 4.5
  arc A1 centre (-151.8464, 140.6117) radius 3.05 clockwise from (-149.6897, 138.455) to (-154.0031, 142.7684)
  arc A2 centre (-173.1597, 140.6117) radius 3.05 clockwise from (-171.0031, 142.7684) to (-175.3164, 138.455)
  arc A3 centre (-185.8464, 140.6117) radius 3.05 clockwise from (-183.6897, 138.455) to (-188.0031, 142.7684)
  arc A4 centre (-207.1597, 140.6117) radius 3.05 clockwise from (-205.0031, 142.7684) to (-209.3164, 138.455)
  circle C2 centre (-196.5031, 144.455) radius 4.5
  circle C3 centre (-162.5031, 144.455) radius 4.5
  circle C4 centre (-196.5031, 6) radius 4.5
  circle C5 centre (-207.1597, 9.8433) radius 3.05
  circle C6 centre (-185.8464, 9.8433) radius 3.05
  circle C7 centre (-173.1597, 9.8433) radius 3.05
  circle C8 centre (-151.8464, 9.8433) radius 3.05
  point P3 (-205.0031, 12)
  point P34 (-205.0031, 12)
  point P6 (-188.0031, 12)
  point P37 (-188.0031, 12)
  point P7 (-171.0031, 12)
  point P40 (-171.0031, 12)
  point P10 (-154.0031, 12)
  point P43 (-154.0031, 12)
  point P46 (-207.1597, 9.8433)
  point P47 (-185.8464, 9.8433)
  point P48 (-173.1597, 9.8433)
  point P49 (-151.8464, 9.8433)
  horizontal L22
  coincident P3 P34
  horizontal L24
  coincident P6 P37
  horizontal L26
  coincident P7 P40
  horizontal L28
  coincident P10 P43
  coincident L21 P46
  coincident L23 P47
  coincident L25 P48
  coincident L27 P49
  dimension "d607" angle L21 L22 = 135
  dimension "d608" angle L23 L24 = 45
  dimension "d609" angle L25 L26 = 135
  dimension "d610" angle L27 L28 = 45
  dimension "d611" diameter C5 = 6.1
  dimension "d612" diameter C6 = 6.1
  dimension "d613" diameter C7 = 6.1
  dimension "d614" diameter C8 = 6.1
  dimension "d615" distance P34 P46 = 3.05
  dimension "d616" distance P37 P47 = 3.05
  dimension "d617" distance P40 P48 = 3.05 (= "d616")
  dimension "d618" distance P43 P49 = 3.05 (= "d617")
extrude "Extrusion106" cut sketch "Skizze104" profile of L1 L3 L4 L5 L7 L8 L20 C5 C6 C7 C8 against normal blind 26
